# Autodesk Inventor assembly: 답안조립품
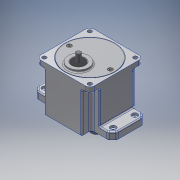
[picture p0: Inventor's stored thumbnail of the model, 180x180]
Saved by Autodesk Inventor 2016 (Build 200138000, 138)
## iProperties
Created: 2017-01
Part Number: 답안조립품
Material: 일반
Document SubType Name: Assembly
Designer: Owner
Author: Owner
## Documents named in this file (10)
- C:\Users\Owner\Desktop\470111V1018\답안조립품.iam
- C:\Users\Owner\Desktop\470111V1018\본체.ipt
- C:\Users\Owner\Desktop\470111V1018\메인축.ipt
- C:\Users\Owner\Desktop\470111V1018\베어링 608.ipt
- C:\Users\Owner\Desktop\470111V1018\베어링 6003.ipt
- C:\Users\Owner\Desktop\470111V1018\볼트 M4 x 10.ipt
- C:\Users\Owner\Desktop\470111V1018\서브축.ipt
- C:\Users\Owner\Desktop\470111V1018\오일실 8 22 7.ipt
- C:\Users\Owner\Desktop\470111V1018\오일실 17 32 8.ipt
- C:\Users\Owner\Desktop\470111V1018\커버.ipt
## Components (2 placed, 1 different names)
1. ISO 4762 M4 x 10:1
2. ISO 4762 M4 x 10:2
